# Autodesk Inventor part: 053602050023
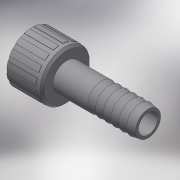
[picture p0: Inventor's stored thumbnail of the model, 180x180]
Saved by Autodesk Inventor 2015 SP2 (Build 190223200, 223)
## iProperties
Created: 2017-10
Part Number: 053602050023
Material: Generic
Description: PLASSON HOSE NOZZLE+NUT/THR. 2.1/4"-50
Document SubType Name: Modeling
Designer: KIM
Density: 1 g/cm^3
Appearance: Default
Author: KIM
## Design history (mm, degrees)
derived "053602.ipt"
feature "Solid1::053602.ipt"
tag "TaggingFeature1"
body "Solid1"
other parameters: "d0" = 104, "d1" = 170 deg, "d5" = 75.3024, "d6" = 35, "d8" = 41.6, "d9" = 62.752, "d10" = 31.2, "d11" = 18.72, "d12" = 26, "d13" = 74.04736, "d14" = 3.1376, "d17" = 6.2752, "d18" = 3.1376, "d19" = 29.12, "d20" = 0, "d22" = 360 deg, "d_" = 16, "H_" = 104, "G_" = 62.752
